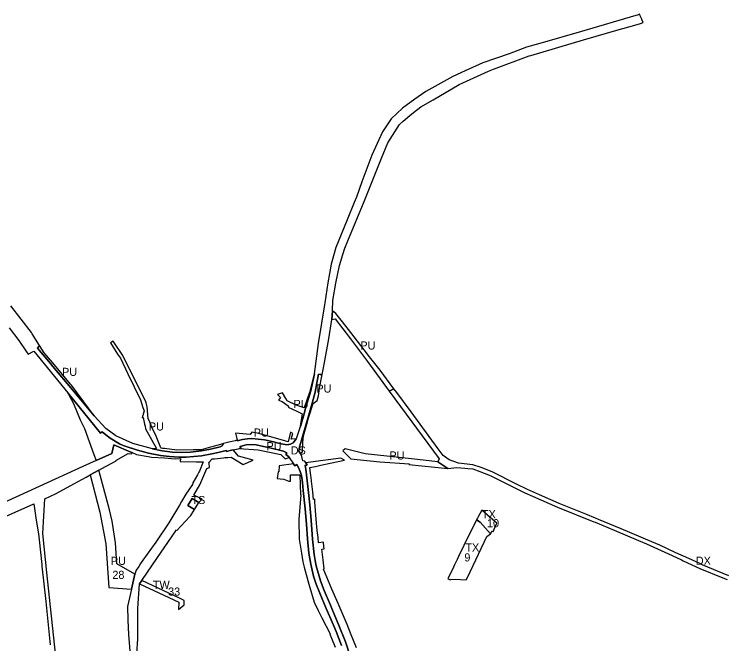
# Model space of a CAD drawing. Extents: x -521882 to -518995, y -1142400 to -1140153.
# Drawn here: x -520739 to -519863, y -1141032 to -1140255 of the extents above; entities that cross this region are included whole.
import ezdxf

# ---------------------------------------------------------------- set-up
doc = ezdxf.new("R2010")
doc.units = 0
for name, color, linetype in [('90320013', 7, 'Continuous'), ('90370013', 7, 'Continuous'), ('90390023', 7, 'Continuous'), ('90410013', 7, 'Continuous'), ('90440023', 7, 'Continuous'), ('90450013', 7, 'Continuous'), ('90450023', 7, 'Continuous'), ('ID_navrh', 7, 'Continuous')]:
    doc.layers.add(name, color=color, linetype=linetype)

msp = doc.modelspace()

# ---------------------------------------------------------------- linework, layer by layer
at = {"layer": '90320013'}
for points in [[(-520346.89, -1140621.24), (-520346.39, -1140608.35), (-520342.68, -1140587.14), (-520337.95, -1140565.45), (-520333.94, -1140551.84), (-520331.42, -1140543.88), (-520327.66, -1140534.75), (-520307.77, -1140486.46), (-520286.11, -1140432.61), (-520278.46, -1140413.78), (-520263.92, -1140391.15), (-520259.52, -1140387.05), (-520251.21, -1140380.2), (-520246.72, -1140376.59), (-520237.84, -1140369.42), (-520222.7, -1140360.61), (-520190.37, -1140341.83), (-520154.29, -1140325.48), (-520148.17, -1140323.1), (-520104.17, -1140306.68), (-520102.1, -1140306.15), (-520037.05, -1140286.83), (-519993.22, -1140274.03), (-519976.66, -1140269.42), (-519967, -1140266.42), (-519963.47, -1140265.25), (-519965.02, -1140261.78), (-519965.23, -1140261.32), (-519967.14, -1140257.04), (-519967.34, -1140256.59), (-519967.99, -1140255.12), (-519970.54, -1140256.24), (-519972.75, -1140256.9), (-520039.59, -1140276.29), (-520091.03, -1140291.29), (-520107.24, -1140295.95), (-520128.63, -1140303.97), (-520161.16, -1140315.09), (-520183.06, -1140324.86), (-520198.24, -1140332), (-520231.71, -1140350.36), (-520245.33, -1140359.99), (-520260.24, -1140370.94), (-520274.33, -1140384.38), (-520285.01, -1140400.23), (-520298.27, -1140429.16), (-520310.52, -1140461.93), (-520317.28, -1140480.73), (-520317.29, -1140480.75), (-520319.85, -1140487.51), (-520328.73, -1140508.82), (-520342.62, -1140543.01), (-520348.21, -1140563.43), (-520352.4, -1140586.73), (-520356.14, -1140611.39), (-520356.59, -1140613.91), (-520364.42, -1140661.36), (-520369.41, -1140698.76), (-520368.79, -1140698.83), (-520370.77, -1140708.37), (-520373.52, -1140720.12), (-520380.21, -1140742.93), (-520381.78, -1140748.3), (-520386.29, -1140763.79), (-520386.83, -1140765.41), (-520391.38, -1140779.15), (-520393.48, -1140782.23), (-520395.36, -1140784.1), (-520398.38, -1140785.83), (-520400.82, -1140786.35), (-520401.42, -1140786.48), (-520404.95, -1140786.22), (-520409.82, -1140785.14), (-520421.16, -1140782.56), (-520430.59, -1140780.58), (-520442.14, -1140779.17), (-520447.03, -1140778.94), (-520451.46, -1140779.1), (-520457.74, -1140780.06), (-520464.21, -1140781.48), (-520464.48, -1140780.47), (-520466.78, -1140781.53), (-520470.41, -1140782.37), (-520474.64, -1140783.36), (-520480.98, -1140785.01), (-520482.88, -1140787.7), (-520485.15, -1140788.87), (-520497.35, -1140791.93), (-520508.09, -1140793.94), (-520521.89, -1140795.42), (-520533.1, -1140795.95), (-520544.08, -1140795.45), (-520556.98, -1140793.85), (-520568.68, -1140791.66), (-520593.15, -1140785.04), (-520614.11, -1140775.58), (-520626.37, -1140766.52), (-520640.71, -1140750.61), (-520667.53, -1140718.71), (-520691.52, -1140689.98), (-520694.71, -1140686.16), (-520710.41, -1140667.24), (-520707.94, -1140663.79), (-520717.09, -1140649.55), (-520718.15, -1140647.9), (-520730.64, -1140631.58), (-520743.28, -1140615.01)], [(-520324.76, -1141047.17), (-520330.66, -1141029.65), (-520339.2, -1141008.34), (-520343.82, -1140997.39), (-520349.32, -1140984.59), (-520356.97, -1140966.32), (-520361.56, -1140954.25), (-520366.72, -1140935.8), (-520368.13, -1140929.14), (-520369.28, -1140921.92), (-520371.26, -1140902.9), (-520373.16, -1140879.42), (-520374.77, -1140860.47), (-520376.29, -1140845.28), (-520379.1, -1140819.91), (-520380.6, -1140811.79), (-520380.67, -1140811.43), (-520380.39, -1140811.76), (-520379.96, -1140811.88), (-520378.82, -1140811.8), (-520377.82, -1140811.29), (-520379.43, -1140808.81), (-520380.85, -1140806.63), (-520383.09, -1140806.25), (-520384.61, -1140800.83), (-520385.85, -1140798.14), (-520388.29, -1140794.2), (-520387.56, -1140789.2), (-520385.08, -1140780.78), (-520382.64, -1140772.35), (-520377.6, -1140755.34), (-520371.69, -1140734.94), (-520368.19, -1140721.56), (-520365.84, -1140710.09), (-520363.79, -1140699.4), (-520361.97, -1140699.61), (-520359.48, -1140699.91), (-520357.72, -1140691.49), (-520356.53, -1140684.75), (-520351.39, -1140655.57), (-520347.36, -1140631.75), (-520346.89, -1140621.24)], [(-520745.42, -1140642.26), (-520733.42, -1140657.97), (-520724.12, -1140671.61), (-520722.11, -1140674.56), (-520715.02, -1140671.04), (-520673.31, -1140722.41), (-520632.98, -1140772.07), (-520630.76, -1140770.61), (-520626.26, -1140774.29), (-520620.79, -1140778.52), (-520609.47, -1140785.27), (-520604.74, -1140787.54), (-520595.11, -1140790.67), (-520594.41, -1140790.88), (-520587.36, -1140792.97), (-520573.73, -1140796.75), (-520558.67, -1140799.71), (-520547.7, -1140801.1), (-520536.39, -1140801.86), (-520527.36, -1140801.68), (-520508.3, -1140799.99), (-520495.6, -1140797.79), (-520487.57, -1140796.09), (-520477.93, -1140793.38), (-520477.5, -1140794.69), (-520471.14, -1140793.15), (-520469.2, -1140792.72), (-520463.08, -1140791.37), (-520461.64, -1140791.05), (-520459.9, -1140790.65), (-520460.51, -1140788.53), (-520453.31, -1140786.74), (-520446.22, -1140786.13), (-520440.68, -1140786.74), (-520435.45, -1140787.73), (-520424.08, -1140790.09), (-520407.29, -1140794.34), (-520402.86, -1140796.64), (-520404.19, -1140798.55), (-520401.05, -1140800.99), (-520400.31, -1140802.09), (-520394.93, -1140810.08), (-520393.28, -1140812.54), (-520391.45, -1140811.33), (-520390.7, -1140810.83), (-520388.5, -1140814.63), (-520386.51, -1140819.33), (-520385.53, -1140823.04), (-520384.67, -1140826.92), (-520383.72, -1140832.94), (-520382.69, -1140842.89), (-520380.29, -1140865.65), (-520378.78, -1140884.3), (-520377.36, -1140902.45), (-520375.75, -1140920.12), (-520373.47, -1140934.03), (-520369.93, -1140948.53), (-520366.71, -1140958.45), (-520362.35, -1140969.44), (-520354.36, -1140988.48), (-520345.5, -1141009.13), (-520342.18, -1141017.11), (-520335.75, -1141034.28)]]:
    msp.add_lwpolyline(points, dxfattribs=at)
at = {"layer": '90370013'}
for points in [[(-520119.77, -1140834.99), (-520149.6, -1140820.02), (-520163.23, -1140814.61), (-520173.51, -1140811.18), (-520191.48, -1140809.25), (-520202.97, -1140805.12), (-520210.31, -1140799.64), (-520216.26, -1140791.5), (-520249.86, -1140745.99), (-520267.51, -1140722.14), (-520270.86, -1140717.61), (-520276.72, -1140720.19), (-520215.27, -1140803.99), (-520216.9, -1140807.42), (-520204.62, -1140815.75), (-520193.39, -1140814.61), (-520183.32, -1140815.4), (-520179.62, -1140815.67), (-520173.51, -1140816.17), (-520164.79, -1140819.27), (-520154.23, -1140823.56), (-520150.53, -1140825.07), (-520127.38, -1140836.75), (-520109.6, -1140845.72), (-520099.84, -1140850.03), (-520069.02, -1140863.47), (-520024.21, -1140881.57), (-520022.73, -1140882.19), (-519999.48, -1140892), (-519969.45, -1140904.62), (-519959.29, -1140908.89), (-519927.83, -1140922.94), (-519916.21, -1140928.63), (-519914.16, -1140929.63), (-519893.61, -1140939.25), (-519865.12, -1140950.76), (-519859.94, -1140952.86)], [(-520679.92, -1141124.76), (-520699.09, -1140943.92), (-520704.17, -1140895.93), (-520701.37, -1140853.35), (-520687.49, -1140846.81), (-520665.74, -1140834.79), (-520650.7, -1140826.31), (-520645.66, -1140823.61), (-520634.79, -1140817.77), (-520631.12, -1140815.76), (-520613.67, -1140806.13), (-520613.82, -1140805.77), (-520598.71, -1140797.27), (-520594.09, -1140797.76), (-520593.85, -1140796.07), (-520595.39, -1140795.43), (-520616.33, -1140786.69), (-520618.93, -1140797.21), (-520638.22, -1140805.93), (-520654.73, -1140813.47), (-520708.35, -1140837.86), (-520882.47, -1140917.37)], [(-519858.03, -1140948.23), (-519890.83, -1140934.46), (-519893.61, -1140933.19), (-519907.29, -1140926.89), (-519923.13, -1140919.66), (-519943.08, -1140910.55), (-519952.82, -1140906.1), (-519990.79, -1140890.22), (-519997.49, -1140887.4), (-520018.57, -1140878.52), (-520022.3, -1140876.95), (-520034.41, -1140872.06), (-520067.09, -1140858.86), (-520091.34, -1140848.28), (-520106.23, -1140841.79), (-520119.77, -1140834.99)], [(-520881.74, -1140933.43), (-520715.12, -1140859.45), (-520712.47, -1140876.54), (-520710.48, -1140889.38), (-520709.39, -1140896.44), (-520708.6, -1140903.84), (-520705.35, -1140934.26), (-520705.13, -1140936.35), (-520700.46, -1140980.02), (-520694.75, -1141033.39)]]:
    msp.add_lwpolyline(points, dxfattribs=at)
at = {"layer": '90390023'}
msp.add_lwpolyline([(-520581.88, -1140953.8), (-520584.75, -1140957.97), (-520560.76, -1140969.3), (-520536.41, -1140980.8), (-520536.52, -1140989.65), (-520529.52, -1140984.06), (-520529.45, -1140978.56), (-520536.34, -1140975.31), (-520548.43, -1140969.6), (-520581.88, -1140953.8)], dxfattribs=at)
at = {"layer": '90410013'}
msp.add_lwpolyline([(-520511.48, -1140857.9), (-520519.8, -1140852.78), (-520525.13, -1140861.38), (-520516.84, -1140866.53), (-520511.48, -1140857.9)], dxfattribs=at)
at = {"layer": '90440023'}
for points in [[(-520168.95, -1140879.03), (-520164.55, -1140881.96), (-520151.68, -1140896.26), (-520149.94, -1140892.73), (-520148.74, -1140894), (-520148.27, -1140892.97), (-520147.23, -1140890.72), (-520143.83, -1140883.35), (-520152.09, -1140876.15), (-520162.5, -1140867.24), (-520166.62, -1140874.78), (-520167.79, -1140876.9)], [(-520168.95, -1140879.03), (-520170.08, -1140881.1), (-520178.74, -1140898.05), (-520184.7, -1140910.65), (-520191.17, -1140924.29), (-520193, -1140928.16), (-520196.08, -1140934.67), (-520197.39, -1140937.44), (-520204.29, -1140951.99), (-520201.3, -1140953.32), (-520201.27, -1140953.32), (-520200.79, -1140952.24), (-520189.01, -1140952.86), (-520181.77, -1140953.24), (-520180.26, -1140950.09), (-520156.19, -1140899.86), (-520151.68, -1140896.26), (-520164.55, -1140881.96)]]:
    msp.add_lwpolyline(points, close=True, dxfattribs=at)
at = {"layer": '90450013'}
for points in [[(-520346.89, -1140621.24), (-520347.36, -1140631.75), (-520343.28, -1140631.04), (-520324.4, -1140655.71), (-520303.56, -1140683.6), (-520276.72, -1140720.19), (-520270.86, -1140717.61), (-520287.89, -1140694.59), (-520300.9, -1140678.05), (-520307.57, -1140669.43), (-520324.2, -1140648.06), (-520334.5, -1140634.63), (-520342.44, -1140624.55), (-520346.89, -1140621.24)], [(-520617.05, -1140658.61), (-520620.66, -1140660.83), (-520611.7, -1140674.57), (-520608.35, -1140679.79), (-520599.29, -1140698.77), (-520583.71, -1140731.03), (-520580.56, -1140740.45), (-520579.16, -1140744.51), (-520581.36, -1140753.24), (-520580.35, -1140753), (-520579.46, -1140756.88), (-520578.47, -1140761.14), (-520577.96, -1140763.57), (-520577.16, -1140766.7), (-520563.9, -1140791.05), (-520568.68, -1140791.66), (-520556.98, -1140793.85), (-520544.08, -1140795.45), (-520533.1, -1140795.95), (-520521.89, -1140795.42), (-520508.09, -1140793.94), (-520497.35, -1140791.93), (-520485.15, -1140788.87), (-520482.88, -1140787.7), (-520480.98, -1140785.01), (-520484.92, -1140786.1), (-520497.16, -1140789.47), (-520508.59, -1140792.61), (-520517.96, -1140792.82), (-520538.73, -1140793.3), (-520553.78, -1140791.02), (-520556.47, -1140791.09), (-520558.14, -1140790.76), (-520558.32, -1140790.33), (-520564.34, -1140775.92), (-520569.37, -1140764.94), (-520571.93, -1140758.73), (-520574.04, -1140754.01), (-520575.25, -1140739.5), (-520576.44, -1140734.91), (-520577.29, -1140732.42), (-520580.64, -1140725.97), (-520586.97, -1140713.22), (-520598.21, -1140690.89), (-520605.12, -1140676.44), (-520617.05, -1140658.61)], [(-520408.23, -1140722.45), (-520414.39, -1140724.32), (-520410.99, -1140728.16), (-520413.15, -1140731.24), (-520408.83, -1140733.26), (-520401.38, -1140738.43), (-520400.87, -1140738.78), (-520401.52, -1140740.13), (-520396.18, -1140742.58), (-520390.88, -1140745.01), (-520384.05, -1140748.14), (-520386.83, -1140765.41), (-520386.29, -1140763.79), (-520381.78, -1140748.3), (-520380.21, -1140742.93), (-520373.52, -1140720.12), (-520370.77, -1140708.37), (-520368.79, -1140698.83), (-520369.41, -1140698.76), (-520375.15, -1140722.06), (-520381.74, -1140740.77), (-520391.43, -1140737.8), (-520402.49, -1140732.06), (-520404.15, -1140729.51), (-520408.23, -1140722.45)], [(-520587.85, -1141044.25), (-520586.99, -1141025.98), (-520586.76, -1141021.16), (-520586.68, -1140988.64), (-520584.75, -1140957.97), (-520581.88, -1140953.8), (-520562.58, -1140925.73), (-520549.95, -1140907.16), (-520539.31, -1140891.51), (-520538.57, -1140892.18), (-520522.62, -1140874.92), (-520521.46, -1140873.68), (-520516.84, -1140866.53), (-520525.13, -1140861.38), (-520519.8, -1140852.78), (-520511.48, -1140857.9), (-520507.49, -1140853.67), (-520517.77, -1140848.71), (-520510.31, -1140835.9), (-520501.75, -1140815.97), (-520498.5, -1140814.52), (-520499.02, -1140809.41), (-520499.12, -1140808.43), (-520495.25, -1140804.01), (-520492.42, -1140803.71), (-520481.31, -1140802.54), (-520479.52, -1140802.35), (-520475.9, -1140802.08), (-520471.87, -1140801.78), (-520456.93, -1140810.9), (-520444.45, -1140805.57), (-520462.48, -1140800.42), (-520469.2, -1140792.72), (-520471.14, -1140793.15), (-520477.5, -1140794.69), (-520477.93, -1140793.38), (-520487.57, -1140796.09), (-520495.6, -1140797.79), (-520508.3, -1140799.99), (-520527.36, -1140801.68), (-520536.39, -1140801.86), (-520547.7, -1140801.1), (-520558.67, -1140799.71), (-520573.73, -1140796.75), (-520587.36, -1140792.97), (-520594.41, -1140790.88), (-520595.11, -1140790.67), (-520604.74, -1140787.54), (-520609.47, -1140785.27), (-520620.79, -1140778.52), (-520626.26, -1140774.29), (-520630.76, -1140770.61), (-520632.98, -1140772.07), (-520673.31, -1140722.41), (-520669.12, -1140730.36), (-520666.3, -1140735.71), (-520657.82, -1140755.57), (-520652.69, -1140766.32), (-520641.11, -1140798.37), (-520638.22, -1140805.93), (-520618.93, -1140797.21), (-520616.33, -1140786.69), (-520595.39, -1140795.43), (-520593.85, -1140796.07), (-520588.57, -1140798.45), (-520573.94, -1140800.9), (-520569.82, -1140801.63), (-520553.77, -1140802.66), (-520540.96, -1140803.77), (-520534.2, -1140803.46), (-520534.78, -1140807.16), (-520514.4, -1140807.37), (-520506.04, -1140807.36), (-520510.91, -1140818.98), (-520511.64, -1140820.3), (-520513.38, -1140823.43), (-520518.98, -1140833.57), (-520519.49, -1140835.7), (-520527.5, -1140847.46), (-520533.13, -1140856.68), (-520535.38, -1140861.16), (-520548.74, -1140883.02), (-520564.56, -1140906.56), (-520580.62, -1140928.87), (-520582.55, -1140931.77), (-520583.47, -1140933.16), (-520585.74, -1140936.61), (-520588.9, -1140941.38), (-520590.36, -1140946.34), (-520594.75, -1140964.79), (-520599.73, -1140986.18), (-520599.09, -1141003), (-520598.4, -1141020.44), (-520598.37, -1141020.83), (-520596.21, -1141046.3)], [(-520466.39, -1140772.32), (-520464.48, -1140780.47), (-520464.21, -1140781.48), (-520457.74, -1140780.06), (-520451.46, -1140779.1), (-520447.03, -1140778.94), (-520442.14, -1140779.17), (-520430.59, -1140780.58), (-520421.16, -1140782.56), (-520409.82, -1140785.14), (-520404.95, -1140786.22), (-520401.42, -1140786.48), (-520400.82, -1140786.35), (-520398.38, -1140785.83), (-520395.36, -1140784.1), (-520393.48, -1140782.23), (-520391.38, -1140779.15), (-520397.56, -1140779.72), (-520395.82, -1140772.4), (-520398.45, -1140770.83), (-520401.54, -1140783.02), (-520419.92, -1140777.53), (-520430.49, -1140774.45), (-520437.68, -1140772.4), (-520446.34, -1140770.88), (-520448.2, -1140773.61), (-520466.39, -1140772.32)], [(-520400.31, -1140802.09), (-520401.05, -1140800.99), (-520404.19, -1140798.55), (-520402.86, -1140796.64), (-520407.29, -1140794.34), (-520424.08, -1140790.09), (-520435.45, -1140787.73), (-520440.68, -1140786.74), (-520446.22, -1140786.13), (-520453.31, -1140786.74), (-520460.51, -1140788.53), (-520459.9, -1140790.65), (-520461.64, -1140791.05), (-520438.34, -1140792.64), (-520410.6, -1140798.4), (-520404.93, -1140803.86), (-520400.31, -1140802.09)], [(-520317.01, -1141037.16), (-520321.6, -1141025.87), (-520323.52, -1141021.14), (-520328.8, -1141008.12), (-520339.88, -1140982.4), (-520347.56, -1140964.58), (-520357.85, -1140939.9), (-520356.86, -1140939.57), (-520358.24, -1140928.5), (-520359.88, -1140915.32), (-520357.13, -1140915.06), (-520357.38, -1140911.92), (-520357.79, -1140906.87), (-520363.85, -1140907.67), (-520364.55, -1140901.11), (-520365.47, -1140892.49), (-520366.29, -1140883.26), (-520368.38, -1140857.16), (-520368.63, -1140853.74), (-520369.93, -1140853.84), (-520371.04, -1140844.39), (-520372.63, -1140831.2), (-520373.19, -1140826.31), (-520373.37, -1140824.7), (-520374.57, -1140814.53), (-520367.81, -1140813.15), (-520362.72, -1140812.11), (-520357.19, -1140810.98), (-520332, -1140805.6), (-520331.98, -1140805.6), (-520336.41, -1140802.99), (-520373.88, -1140807.82), (-520379.43, -1140808.81), (-520377.82, -1140811.29), (-520378.82, -1140811.8), (-520379.96, -1140811.88), (-520380.39, -1140811.76), (-520380.67, -1140811.43), (-520380.6, -1140811.79), (-520379.1, -1140819.91), (-520376.29, -1140845.28), (-520374.77, -1140860.47), (-520373.16, -1140879.42), (-520371.26, -1140902.9), (-520369.28, -1140921.92), (-520368.13, -1140929.14), (-520366.72, -1140935.8), (-520361.56, -1140954.25), (-520356.97, -1140966.32), (-520349.32, -1140984.59), (-520343.82, -1140997.39), (-520339.2, -1141008.34), (-520330.66, -1141029.65), (-520324.76, -1141047.17)], [(-520335.75, -1141034.28), (-520342.18, -1141017.11), (-520345.5, -1141009.13), (-520354.36, -1140988.48), (-520362.35, -1140969.44), (-520366.71, -1140958.45), (-520369.93, -1140948.53), (-520373.47, -1140934.03), (-520375.75, -1140920.12), (-520377.36, -1140902.45), (-520378.78, -1140884.3), (-520380.29, -1140865.65), (-520382.69, -1140842.89), (-520383.72, -1140832.94), (-520384.67, -1140826.92), (-520385.53, -1140823.04), (-520386.51, -1140819.33), (-520388.5, -1140814.63), (-520390.7, -1140810.83), (-520391.45, -1140811.33), (-520393.28, -1140812.54), (-520394.93, -1140810.08), (-520412.34, -1140812.28), (-520412.85, -1140819.83), (-520413.68, -1140819.71), (-520414.81, -1140828.01), (-520411.4, -1140828.34), (-520406.52, -1140828.82), (-520400.46, -1140831.36), (-520398.31, -1140831.29), (-520398.57, -1140823.79), (-520386.88, -1140823.39), (-520386.02, -1140848.4), (-520385.81, -1140848.46), (-520388.38, -1140878.81), (-520387.91, -1140902.86), (-520385, -1140920.46), (-520383.27, -1140930.85), (-520381.51, -1140937.64), (-520376.07, -1140958.44), (-520369.44, -1140980.74), (-520364.35, -1140991.14), (-520359.98, -1141000.07), (-520349.61, -1141019.9), (-520350.1, -1141020.17), (-520347.88, -1141025.34), (-520343.25, -1141036.1)]]:
    msp.add_lwpolyline(points, dxfattribs=at)
for points in [[(-520691.74, -1140685.4), (-520702.26, -1140672.84), (-520707.94, -1140663.79), (-520710.41, -1140667.24), (-520694.71, -1140686.16), (-520691.52, -1140689.98), (-520667.53, -1140718.71), (-520640.71, -1140750.61), (-520653.49, -1140733.31), (-520668.57, -1140712.91), (-520669.79, -1140711.59)], [(-520385.85, -1140798.14), (-520385.62, -1140796.31), (-520383.53, -1140795.4), (-520383.46, -1140783.32), (-520382.29, -1140775.26), (-520378.38, -1140760.91), (-520376.29, -1140753.27), (-520370.5, -1140735.37), (-520365.68, -1140731.9), (-520364.02, -1140726.04), (-520363.02, -1140719.82), (-520362.54, -1140716.5), (-520359.48, -1140699.91), (-520361.97, -1140699.61), (-520363.79, -1140699.4), (-520365.84, -1140710.09), (-520368.19, -1140721.56), (-520371.69, -1140734.94), (-520377.6, -1140755.34), (-520382.64, -1140772.35), (-520385.08, -1140780.78), (-520387.56, -1140789.2), (-520388.29, -1140794.2)], [(-520333.88, -1140793.93), (-520323.97, -1140803.87), (-520288.38, -1140807.41), (-520251.92, -1140810), (-520252.34, -1140811), (-520204.62, -1140815.75), (-520216.9, -1140807.42), (-520249.32, -1140803.75), (-520306.3, -1140797.86), (-520331.09, -1140791.46)]]:
    msp.add_lwpolyline(points, close=True, dxfattribs=at)
at = {"layer": '90450023'}
msp.add_lwpolyline([(-520634.79, -1140817.77), (-520645.66, -1140823.61), (-520633.62, -1140869.48), (-520626.29, -1140908.87), (-520622.44, -1140962.75), (-520594.75, -1140964.79), (-520590.36, -1140946.34), (-520612.5, -1140933.48), (-520614.37, -1140907.34), (-520618.56, -1140880.81), (-520621.9, -1140866.86), (-520634.79, -1140817.77)], dxfattribs=at)

# ---------------------------------------------------------------- texts
at = {"layer": '90320013'}
msp.add_text('DS', height=10, rotation=360, dxfattribs=at).set_placement((-520398.23, -1140798.44))
at = {"layer": '90370013'}
msp.add_text('DX', height=10, rotation=0, dxfattribs=at).set_placement((-519898.57, -1140934.56))
at = {"layer": '90390023'}
msp.add_text('TW', height=10, dxfattribs=at).set_placement((-520568.31, -1140964.35))
at = {"layer": '90410013'}
msp.add_text('TS', height=10, rotation=0, dxfattribs=at).set_placement((-520520.73, -1140859.64))
at = {"layer": '90440023'}
for p in [(-520162.44, -1140877.16), (-520182.81, -1140918.26)]:
    msp.add_text('TX', height=10, rotation=0, dxfattribs=at).set_placement(p)
at = {"layer": '90450013'}
for rotation, p in [(360, (-520312.33, -1140668.96)), (360, (-520680.29, -1140701.53)), (360, (-520366.59, -1140722.1)), (360, (-520394.76, -1140741.15)), (360, (-520573.19, -1140768.89)), (0, (-520443.86, -1140776.4)), (360, (-520428.08, -1140793.17)), (360, (-520276.49, -1140804.68))]:
    msp.add_text('PU', height=10, rotation=rotation, dxfattribs=at).set_placement(p)
at = {"layer": '90450023'}
msp.add_text('PU', height=10, rotation=0, dxfattribs=at).set_placement((-520620.01, -1140934.76))
at = {"layer": 'ID_navrh'}
for s, rotation, p in [('10', 360, (-520156.12, -1140888.21)), ('9', 360, (-520184.05, -1140930.46)), ('28', 0, (-520618.21, -1140951.99))]:
    msp.add_text(s, height=10, rotation=rotation, dxfattribs=at).set_placement(p)
msp.add_text('33', height=10, dxfattribs=at).set_placement((-520549.48, -1140972.66))

doc.saveas('drawing.dxf')
